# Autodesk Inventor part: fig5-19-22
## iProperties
Created: 2004-05
Part Number: fig5-19-22
Document SubType Name: Modeling
Designer: CADCIM Technologies
Manufacturer: Standard
Standards Organization: Custom
Density: 1 g/cm^3
Author: CADCIM Technologies
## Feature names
1. Extrusion1
2. Fillet1
